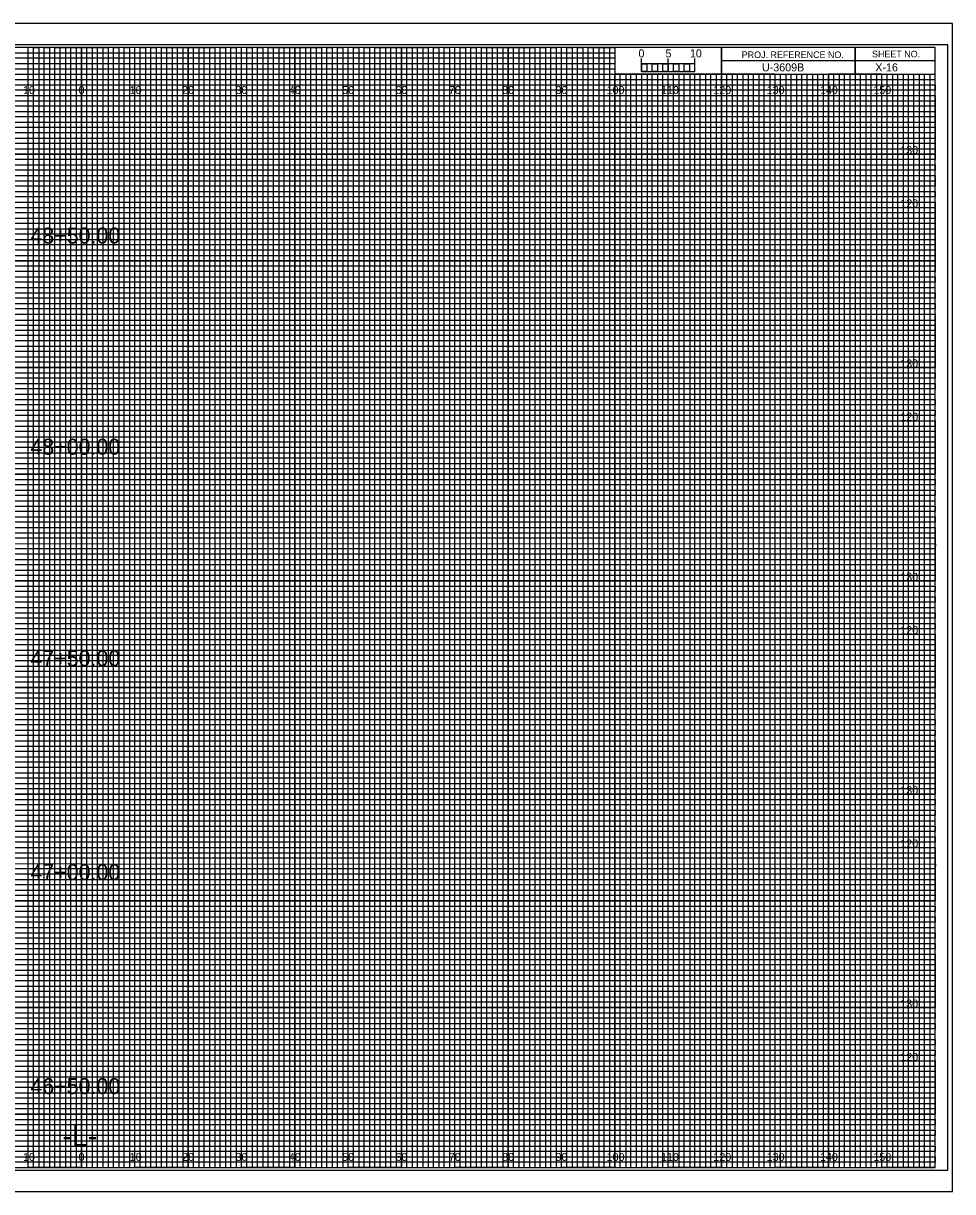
# Model space of a CAD drawing. Extents: x -13 to 329, y -17 to 10994.
# Drawn here: x 149.1 to 323.3, y 3075.5 to 3294.5 of the extents above; entities that cross this region are included whole.
import ezdxf

# ---------------------------------------------------------------- set-up
doc = ezdxf.new("R2010")
doc.units = 0
for name, color, linetype in [('Prop XS Alignment Label', 7, 'Continuous'), ('Prop XS Bar Scale Labels', 7, 'Continuous'), ('Prop XS Elevation Labels', 7, 'Continuous'), ('Prop XS Offset Labels', 7, 'Continuous'), ('Prop XS Project Number', 7, 'Continuous'), ('Prop XS Sheet Number', 7, 'Continuous'), ('Prop XS Station Labels', 7, 'Continuous'), ('Sheet Cross Section CELL', 7, 'Continuous'), ('Sheet Cross Section Grid Major CELL', 7, 'Continuous'), ('Sheet Cross Section Grid Middle CELL', 7, 'Continuous'), ('Sheet Cross Section Grid Minor 1 CELL', 7, 'Continuous'), ('Sheet Cross Section Grid Minor 2 CELL', 7, 'Continuous'), ('Sheet Cross Section Scale CELL', 7, 'Continuous'), ('Sheet Cutting Line CELL', 7, 'Continuous'), ('Sheet DOT Grid CELL', 7, 'Continuous'), ('Sheet Plot Border Inside CELL', 7, 'Continuous'), ('Sheet Plot Border Outside CELL', 7, 'Continuous')]:
    doc.layers.add(name, color=color, linetype=linetype)

msp = doc.modelspace()

# ---------------------------------------------------------------- linework, layer by layer
at = {"layer": 'Sheet Cross Section CELL'}
for p, q in [((305, 3290), (305, 3285)), ((305, 3285), (305, 3290)), ((280, 3287.5), (280, 3285)), ((320, 3287.49), (280, 3287.49)), ((280, 3285), (320, 3285))]:
    msp.add_line(p, q, dxfattribs=at)
for points in [[(320, 3290), (0, 3290), (0, 3080), (320, 3080)], [(280, 3290), (260, 3290), (260, 3285.03), (280, 3285.03)], [(320, 3290), (280, 3290), (280, 3285), (320, 3285)]]:
    msp.add_lwpolyline(points, close=True, dxfattribs=at)
at = {"layer": 'Sheet Cross Section Grid Major CELL'}
for p, q in [((150, 3290), (140, 3290)), ((150, 3080), (150, 3290)), ((170, 3290), (160, 3290)), ((160, 3290), (160, 3080)), ((170, 3080), (170, 3290)), ((190, 3290), (180, 3290)), ((180, 3290), (180, 3080)), ((190, 3080), (190, 3290)), ((210, 3290), (200, 3290)), ((200, 3290), (200, 3080)), ((210, 3080), (210, 3290)), ((230, 3290), (220, 3290)), ((220, 3290), (220, 3080)), ((230, 3080), (230, 3290)), ((250, 3290), (240, 3290)), ((240, 3290), (240, 3080)), ((250, 3080), (250, 3290)), ((260, 3290), (260, 3080)), ((270, 3080), (270, 3285)), ((290, 3285), (280, 3285)), ((280, 3285), (280, 3080)), ((290, 3080), (290, 3285)), ((310, 3285), (300, 3285)), ((300, 3285), (300, 3080)), ((310, 3080), (310, 3285)), ((160, 3080), (150, 3080)), ((180, 3080), (170, 3080)), ((200, 3080), (190, 3080)), ((220, 3080), (210, 3080)), ((240, 3080), (230, 3080)), ((260, 3080), (250, 3080)), ((280, 3080), (270, 3080)), ((300, 3080), (290, 3080)), ((320, 3080), (310, 3080)), ((320, 3080), (320, 3080))]:
    msp.add_line(p, q, dxfattribs=at)
for points in [[(0, 3280), (320, 3280), (320, 3270), (0, 3270)], [(0, 3260), (320, 3260), (320, 3250), (0, 3250)], [(0, 3240), (320, 3240), (320, 3230), (0, 3230)], [(0, 3220), (320, 3220), (320, 3210), (0, 3210)], [(0, 3200), (320, 3200), (320, 3190), (0, 3190)], [(0, 3180), (320, 3180), (320, 3170), (0, 3170)], [(0, 3160), (320, 3160), (320, 3150), (0, 3150)], [(0, 3140), (320, 3140), (320, 3130), (0, 3130)], [(0, 3120), (320, 3120), (320, 3110), (0, 3110)], [(0, 3100), (320, 3100), (320, 3090), (0, 3090)]]:
    msp.add_lwpolyline(points, dxfattribs=at)
at = {"layer": 'Sheet Cross Section Grid Middle CELL'}
for points in [[(145, 3080), (155, 3080), (155, 3290), (165, 3290), (165, 3080), (175, 3080), (175, 3290), (185, 3290), (185, 3080), (195, 3080), (195, 3290), (205, 3290), (205, 3080), (215, 3080), (215, 3290), (225, 3290), (225, 3080), (235, 3080), (235, 3290), (245, 3290), (245, 3080), (255, 3080), (255, 3290), (259.93, 3290), (260, 3290), (260, 3285), (264.99, 3285), (264.99, 3080), (275, 3080), (275, 3285), (285, 3285), (285, 3080), (295, 3080), (295, 3285), (305, 3285), (305, 3080), (315, 3080), (315, 3285)], [(0, 3285), (275, 3285)], [(0, 3265), (320, 3265), (320, 3275), (0, 3275)], [(0, 3245), (320, 3245), (320, 3255), (0, 3255)], [(0, 3225), (320, 3225), (320, 3235), (0, 3235)], [(0, 3205), (320, 3205), (320, 3215), (0, 3215)], [(0, 3185), (320, 3185), (320, 3195), (0, 3195)], [(0, 3165), (320, 3165), (320, 3175), (0, 3175)], [(0, 3145), (320, 3145), (320, 3155), (0, 3155)], [(0, 3125), (320, 3125), (320, 3135), (0, 3135)], [(0, 3105), (320, 3105), (320, 3115), (0, 3115)], [(0, 3085), (320, 3085), (320, 3095), (0, 3095)]]:
    msp.add_lwpolyline(points, dxfattribs=at)
at = {"layer": 'Sheet Cross Section Grid Minor 1 CELL'}
for p, q in [((0, 3289), (260, 3289)), ((260, 3287.98), (0, 3287.98)), ((260, 3289), (260, 3287.98)), ((0, 3287), (260, 3287)), ((260, 3285.89), (0, 3285.89)), ((260, 3287), (260, 3285.89)), ((0, 3284), (320, 3284))]:
    msp.add_line(p, q, dxfattribs=at)
for points in [[(0, 3283), (270, 3283), (320, 3283), (320, 3282), (0, 3282)], [(0, 3281), (320, 3281), (320, 3279), (0, 3279)], [(0, 3278), (320, 3278), (320, 3277), (0, 3276.98)], [(0, 3276), (320, 3276), (320, 3274), (0, 3274)], [(0, 3273), (320, 3273), (320, 3272), (0, 3272)], [(0, 3271), (320, 3271), (320, 3269), (0, 3269)], [(0, 3268), (320, 3268), (320, 3267), (0, 3267)], [(0, 3266), (320, 3266), (320, 3264), (0, 3264)], [(0, 3263), (320, 3263), (320, 3262), (0, 3262)], [(0, 3261), (320, 3261), (320, 3259), (0, 3259)], [(0, 3258), (320, 3258), (320, 3257), (0, 3257)], [(0, 3256), (320, 3256), (320, 3253.95), (320, 3253), (320, 3252), (0, 3252)], [(0, 3254), (320, 3254), (320, 3253), (0, 3253)], [(0, 3251), (320, 3251), (320, 3249), (0, 3249.03)], [(0, 3249.03), (320, 3249), (320, 3248), (0, 3248)], [(0, 3247), (320, 3247), (320, 3246), (0, 3246)], [(0, 3244), (320, 3244), (320, 3243), (0, 3243)], [(0, 3242), (320, 3242), (320, 3241), (0, 3241)], [(-0.07, 3238.89), (320, 3238.89), (320, 3237.88), (-0.07, 3237.88)], [(0, 3237), (320, 3237), (320, 3236), (0, 3236)], [(0, 3234), (320, 3234), (320, 3233), (0, 3233)], [(0, 3232), (320, 3232), (320, 3231), (0, 3231)], [(0, 3229), (320, 3229), (320, 3228), (0, 3228)], [(0, 3227), (320, 3227), (320, 3226), (0, 3226)], [(0, 3224), (320, 3224), (320, 3223), (0, 3223)], [(0, 3222), (320, 3222), (320, 3221), (0, 3221)], [(0, 3219), (320, 3219), (319.99, 3217.98), (0, 3218)], [(0, 3217), (320, 3217), (320, 3216), (0, 3216)], [(0, 3214), (320, 3214), (320, 3213), (0, 3213)], [(0, 3212), (320, 3212), (320, 3211), (0, 3211)], [(0, 3209), (320, 3209), (320, 3208), (0, 3208)], [(0, 3207), (320, 3207), (320, 3206), (0, 3206)], [(0, 3204), (320, 3204), (320, 3203), (0, 3203)], [(0, 3202), (320, 3202), (320, 3201), (0, 3201)], [(0, 3199), (320, 3199), (320, 3198), (0, 3198)], [(0, 3196.99), (320.07, 3196.91), (320, 3196), (0, 3196)], [(0, 3194), (320, 3194), (320, 3193), (0, 3193)], [(0, 3192), (320, 3192), (320, 3191), (0, 3191)], [(0, 3189), (320, 3189), (320, 3188), (0, 3188)], [(0, 3187), (320, 3187), (320, 3186), (0, 3186)], [(0, 3184), (320, 3184), (320, 3183), (0, 3183)], [(0, 3182), (320, 3182), (320, 3181), (0, 3181)], [(0, 3179), (320, 3179), (320, 3178), (0, 3178)], [(0, 3177), (320, 3177), (320, 3176), (0, 3176)], [(0, 3174), (320, 3174), (320, 3173), (0, 3173)], [(0, 3172), (320, 3172), (320, 3171), (0, 3171)], [(0, 3169), (320, 3169), (320, 3168), (0, 3168)], [(0, 3167), (320, 3167), (320, 3166), (0, 3166)], [(0, 3164), (320, 3164), (320, 3163), (0, 3163)], [(0, 3162), (320, 3162), (320, 3161), (0, 3161)], [(0, 3159), (320, 3159), (319.99, 3157.98), (0, 3158)], [(0, 3157), (320, 3157), (320, 3156), (0, 3156)], [(0, 3154), (320, 3154), (320, 3153), (0, 3153)], [(0, 3152), (320, 3152), (320, 3151), (0, 3151)], [(0, 3149), (320, 3149), (320, 3148), (0, 3148)], [(0, 3147), (320, 3147), (320, 3146), (0, 3146)], [(0, 3144), (320, 3144), (320, 3143), (0, 3143)], [(0, 3142), (320, 3142), (320, 3141), (0, 3141)], [(0, 3139), (320, 3139), (320, 3138), (0, 3138)], [(0, 3136.99), (320.07, 3136.91), (320, 3136), (0, 3136)], [(0, 3134), (320, 3134), (320, 3133), (0, 3133)], [(0, 3132), (320, 3132), (320, 3131), (0, 3131)], [(0, 3129), (320, 3129), (320, 3128), (0, 3128)], [(0, 3127), (320, 3127), (320, 3126), (0, 3126)], [(0, 3124), (320, 3124), (320, 3123), (0, 3123)], [(0, 3122), (320, 3122), (320, 3121), (0, 3121)], [(0, 3119), (320, 3119), (320, 3118), (0, 3118)], [(0, 3117), (320, 3117), (320, 3116), (0, 3116)], [(0, 3114), (320, 3114), (320, 3113), (0, 3113)], [(0, 3112), (320, 3112), (320, 3111), (0, 3111)], [(0, 3109), (320, 3109), (320, 3108), (0, 3108)], [(0, 3107), (320, 3107), (320, 3106), (0, 3106)], [(0, 3104), (320, 3104), (320, 3103), (0, 3103)], [(0, 3102), (320, 3102), (320, 3101), (0, 3101)], [(0, 3099), (320, 3099), (320, 3098), (0, 3098)], [(0, 3097), (320, 3097), (320, 3096), (0, 3096)], [(0, 3094), (320, 3094), (320, 3093), (0, 3093)], [(0, 3092), (320, 3092), (320, 3091), (0, 3091)], [(0, 3089), (320, 3089), (320, 3088), (0, 3088)], [(0, 3087), (320, 3087), (320, 3086), (0, 3086)], [(0, 3084), (320, 3084), (320, 3083), (0, 3083)], [(0, 3082), (320, 3082), (320, 3081), (0, 3081)]]:
    msp.add_lwpolyline(points, dxfattribs=at)
at = {"layer": 'Sheet Cross Section Grid Minor 2 CELL'}
for p, q in [((267, 3285), (266.01, 3285)), ((266.01, 3285), (266.01, 3080)), ((267, 3080), (267, 3285)), ((269, 3285), (268, 3285)), ((268, 3285), (268, 3080)), ((269, 3080), (269, 3285)), ((266.01, 3080), (265, 3080)), ((268, 3080), (267, 3080))]:
    msp.add_line(p, q, dxfattribs=at)
for points in [[(150, 3080), (151, 3080), (151, 3290), (152, 3290), (152, 3080)], [(152, 3080), (153, 3080), (153, 3290), (154, 3290), (154, 3080)], [(155, 3080), (156, 3080), (156, 3290), (157, 3290), (157, 3080)], [(157, 3080), (158, 3080), (158, 3290), (159, 3290), (159, 3080)], [(160, 3080), (161, 3080), (161, 3290), (162, 3290), (162, 3080)], [(162, 3080), (163, 3080), (163, 3290), (164, 3290), (164, 3080)], [(165, 3080), (166, 3080), (166, 3290), (167, 3290), (167, 3080)], [(167, 3080), (168, 3080), (168, 3290), (169, 3290), (169, 3080)], [(170, 3080), (171, 3080), (171, 3290), (172, 3290), (172, 3080)], [(172, 3080), (173, 3080), (173, 3290), (174, 3290), (174, 3080)], [(175, 3080), (176, 3080), (176, 3290), (177, 3290), (177, 3080)], [(177, 3080), (178, 3080), (178, 3290), (179, 3290), (179, 3080)], [(180, 3080), (181, 3080), (181, 3290), (182, 3290), (182, 3080)], [(182, 3080), (183, 3080), (183, 3290), (184, 3290), (184, 3080)], [(185, 3080), (186, 3080), (186, 3290), (187, 3290), (187, 3080)], [(187, 3080), (188, 3080), (188, 3290), (189, 3290), (189, 3080)], [(190, 3080), (191, 3080), (191, 3290), (192, 3290), (192, 3080)], [(192, 3080), (193, 3080), (193, 3290), (194, 3290), (194, 3080)], [(195, 3080), (196, 3080), (196, 3290), (197, 3290), (197, 3080)], [(197, 3080), (198, 3080), (198, 3290), (199, 3290), (199, 3080)], [(200, 3080), (201, 3080), (201, 3290), (202, 3290), (202, 3080)], [(202, 3080), (203, 3080), (203, 3290), (204, 3290), (204, 3080)], [(205, 3080), (206, 3080), (206, 3290), (207, 3290), (207, 3080)], [(207, 3080), (208, 3080), (208, 3290), (209, 3290), (209, 3080)], [(210, 3080), (211, 3080), (211, 3290), (212, 3290), (212, 3080)], [(212, 3080), (213, 3080), (213, 3290), (214, 3290), (214, 3080)], [(215, 3080), (216, 3080), (216, 3290), (217, 3290), (217, 3080)], [(217, 3080), (218, 3080), (218, 3290), (219, 3290), (219, 3080)], [(220, 3080), (221, 3080), (221, 3290), (222, 3290), (222, 3080)], [(222, 3080), (223, 3080), (223, 3290), (224, 3290), (224, 3080)], [(225, 3080), (226, 3080), (226, 3290), (227, 3290), (227, 3080)], [(227, 3080), (228, 3080), (228, 3290), (229, 3290), (229, 3080)], [(230, 3080), (231, 3080), (231, 3290), (232, 3290), (232, 3080)], [(232, 3080), (233, 3080), (233, 3290), (234, 3290), (234, 3080)], [(235, 3080), (236, 3080), (236, 3290), (237, 3290), (237, 3080)], [(237, 3080), (238, 3080), (238, 3290), (239, 3290), (239, 3080)], [(240, 3080), (241, 3080), (241, 3290), (242, 3290), (242, 3080)], [(242, 3080), (243, 3080), (243, 3290), (244, 3290), (244, 3080)], [(245, 3080), (246, 3080), (246, 3290), (247, 3290), (247, 3080)], [(247, 3080), (248, 3080), (248, 3290), (249, 3290), (249, 3080)], [(250, 3080), (251, 3080), (251, 3290), (252, 3290), (252, 3080)], [(252, 3080), (253, 3080), (253, 3290), (254, 3290), (254, 3080)], [(255, 3080), (256, 3080), (256, 3290), (257, 3290), (257, 3080)], [(257, 3080), (258, 3080), (258, 3290), (259, 3290), (259, 3080)], [(260, 3080), (261, 3080), (261, 3285), (262.02, 3285), (262.02, 3080)], [(262, 3080), (263, 3080), (263, 3285), (263.99, 3285), (263.99, 3080)], [(270, 3080), (270.98, 3080), (270.98, 3285), (272, 3285), (272, 3080)], [(272, 3080), (273, 3080), (273, 3285), (274.05, 3285), (274.05, 3080)], [(275, 3080), (276, 3080), (276, 3285), (277, 3285), (277, 3080)], [(277, 3080), (278, 3080), (278, 3285), (279, 3285), (279, 3080)], [(280, 3080), (281, 3080), (281, 3285), (282, 3285), (282, 3080)], [(282, 3080), (283, 3080), (283, 3285), (284, 3285), (284, 3080)], [(285, 3080), (286, 3080), (286, 3285), (287, 3285), (287, 3080)], [(287, 3080), (288, 3080), (288, 3285), (289, 3285), (289, 3080)], [(290, 3080), (291, 3080), (291, 3285), (292, 3285), (292, 3080)], [(292, 3080), (293, 3080), (293, 3285), (294, 3285), (294, 3080)], [(295, 3080), (296, 3080), (296, 3285), (297, 3285), (297, 3080)], [(297, 3080), (298, 3080), (298, 3285), (299, 3285), (299, 3080)], [(300, 3080), (301, 3080), (301, 3285), (302, 3285), (302, 3080)], [(302, 3080), (303, 3080), (303, 3285), (304, 3285), (304, 3080)], [(305, 3080), (306, 3080), (306, 3285), (307, 3285), (307, 3080)], [(307, 3080), (308, 3080), (308, 3285), (309, 3285), (309, 3080)], [(310, 3080), (311, 3080), (311, 3285), (312, 3285), (312, 3080)], [(312, 3080), (313, 3080), (313, 3285), (314, 3285), (314, 3080)], [(315, 3080), (316, 3080), (316, 3285), (317, 3285), (317, 3080)], [(317, 3080), (318, 3080), (318, 3285), (319, 3285), (319, 3080)]]:
    msp.add_lwpolyline(points, dxfattribs=at)
at = {"layer": 'Sheet Cross Section Scale CELL'}
for p, q in [((265, 3285.49), (265, 3287.9)), ((265, 3286.9), (265, 3287.9)), ((270, 3285.49), (270, 3287.9)), ((275, 3285.49), (275, 3287.9)), ((275, 3286.9), (275, 3287.9))]:
    msp.add_line(p, q, dxfattribs=at)
for points in [[(275, 3286.9), (265, 3286.9), (265, 3285.49), (275, 3285.49)], [(265, 3286.9), (266, 3286.9), (266, 3285.49), (265, 3285.49)], [(267, 3286.9), (268, 3286.9), (268, 3285.49), (267, 3285.49)], [(269, 3286.9), (270, 3286.9), (270, 3285.49), (269, 3285.49)], [(271, 3286.9), (272, 3286.9), (272, 3285.49), (271, 3285.49)], [(273, 3286.9), (274, 3286.9), (274, 3285.49), (273, 3285.49)]]:
    msp.add_lwpolyline(points, close=True, dxfattribs=at)
at = {"layer": 'Sheet Cutting Line CELL'}
for p, q in [((323.3, 3294.5), (-13.4, 3294.5)), ((-13.4, 3075.5), (323.3, 3075.5))]:
    msp.add_line(p, q, dxfattribs=at)
at = {"layer": 'Sheet DOT Grid CELL'}
for p, q in [((150, 3080), (150, 3290)), ((160, 3080), (160, 3290)), ((170, 3080), (170, 3290)), ((180, 3080), (180, 3290)), ((190, 3080), (190, 3290)), ((200, 3080), (200, 3290)), ((210, 3080), (210, 3290)), ((220, 3080), (220, 3290)), ((230, 3080), (230, 3290)), ((240, 3080), (240, 3290)), ((250, 3080), (250, 3290)), ((260, 3080), (260, 3284.69)), ((270, 3080), (270, 3284.69)), ((280, 3080), (280, 3284.69)), ((290, 3080), (290, 3284.69)), ((300, 3080), (300, 3284.69)), ((310, 3080), (310, 3284.69)), ((0, 3280), (320, 3280)), ((0, 3270), (320, 3270)), ((0, 3260), (320, 3260)), ((0, 3250), (320, 3250)), ((0, 3240), (320, 3240)), ((0, 3230), (320, 3230)), ((0, 3220), (320, 3220)), ((0, 3210), (320, 3210)), ((0, 3200), (320, 3200)), ((0, 3190), (320, 3190)), ((0, 3180), (320, 3180)), ((0, 3170), (320, 3170)), ((0, 3160), (320, 3160)), ((0, 3150), (320, 3150)), ((0, 3140), (320, 3140)), ((0, 3130), (320, 3130)), ((0, 3120), (320, 3120)), ((0, 3110), (320, 3110)), ((0, 3100), (320, 3100)), ((0, 3090), (320, 3090))]:
    msp.add_line(p, q, dxfattribs=at)
at = {"layer": 'Sheet Plot Border Inside CELL'}
msp.add_lwpolyline([(-10.8, 3079.5), (322.4, 3079.5), (322.4, 3290.5), (-10.8, 3290.5)], close=True, dxfattribs=at)
at = {"layer": 'Sheet Plot Border Outside CELL'}
msp.add_lwpolyline([(-13.4, 3075.5), (323.3, 3075.5), (323.3, 3294.5), (-13.4, 3294.5)], close=True, dxfattribs=at)

# ---------------------------------------------------------------- texts
at = {"layer": 'Prop XS Alignment Label'}
msp.add_text('-L-', height=4, dxfattribs=at).set_placement((156.42, 3084))
at = {"layer": 'Prop XS Bar Scale Labels'}
for s, p in [('5', (269.47, 3288.12)), ('10', (274.04, 3288.12))]:
    msp.add_text(s, height=1.5, dxfattribs=at).set_placement(p)
at = {"layer": 'Prop XS Elevation Labels'}
for s, p in [('130', (313.49, 3270)), ('120', (313.5, 3260)), ('130', (313.49, 3230)), ('120', (313.5, 3220)), ('130', (313.49, 3190)), ('120', (313.5, 3180)), ('130', (313.49, 3150)), ('120', (313.5, 3140)), ('130', (313.49, 3110)), ('120', (313.5, 3100))]:
    msp.add_text(s, height=1.5, dxfattribs=at).set_placement(p)
at = {"layer": 'Prop XS Offset Labels'}
for s, p in [('10', (149.04, 3281.25)), ('0', (159.45, 3281.25)), ('0', (159.45, 3281.25)), ('10', (169.04, 3281.25)), ('20', (178.86, 3281.25)), ('30', (188.86, 3281.25)), ('40', (198.86, 3281.25)), ('50', (208.86, 3281.25)), ('60', (218.86, 3281.25)), ('70', (228.86, 3281.25)), ('80', (238.86, 3281.25)), ('90', (248.86, 3281.25)), ('100', (258.44, 3281.25)), ('110', (268.62, 3281.25)), ('120', (278.44, 3281.25)), ('130', (288.44, 3281.25)), ('140', (298.44, 3281.25)), ('150', (308.44, 3281.25)), ('10', (149.04, 3081.25)), ('0', (159.45, 3081.25)), ('0', (159.45, 3081.25)), ('10', (169.04, 3081.25)), ('20', (178.86, 3081.25)), ('30', (188.86, 3081.25)), ('40', (198.86, 3081.25)), ('50', (208.86, 3081.25)), ('60', (218.86, 3081.25)), ('70', (228.86, 3081.25)), ('80', (238.86, 3081.25)), ('90', (248.86, 3081.25)), ('100', (258.44, 3081.25)), ('110', (268.62, 3081.25)), ('120', (278.44, 3081.25)), ('130', (288.44, 3081.25)), ('140', (298.44, 3081.25)), ('150', (308.44, 3081.25))]:
    msp.add_text(s, height=1.5, dxfattribs=at).set_placement(p)
at = {"layer": 'Prop XS Project Number'}
msp.add_text('U-3609B', height=1.5, dxfattribs=at).set_placement((287.56, 3285.5))
at = {"layer": 'Prop XS Sheet Number'}
msp.add_text('X-16', height=1.5, dxfattribs=at).set_placement((308.8, 3285.5))
at = {"layer": 'Prop XS Station Labels'}
for s, p in [('48+50.00', (150.41, 3253.23)), ('48+00.00', (150.41, 3213.64)), ('47+50.00', (150.41, 3173.98)), ('47+00.00', (150.41, 3133.9)), ('46+50.00', (150.41, 3093.78))]:
    msp.add_text(s, height=3, dxfattribs=at).set_placement(p)
at = {"layer": 'Sheet Cross Section CELL'}
for s, p in [('SHEET NO.', (308.19, 3288.12)), ('PROJ. REFERENCE NO.', (283.77, 3287.99))]:
    msp.add_text(s, height=1.25, dxfattribs=at).set_placement(p)
at = {"layer": 'Sheet Cross Section Scale CELL'}
msp.add_text('0', height=1.5, dxfattribs=at).set_placement((264.41, 3288.12))

doc.saveas('drawing.dxf')
